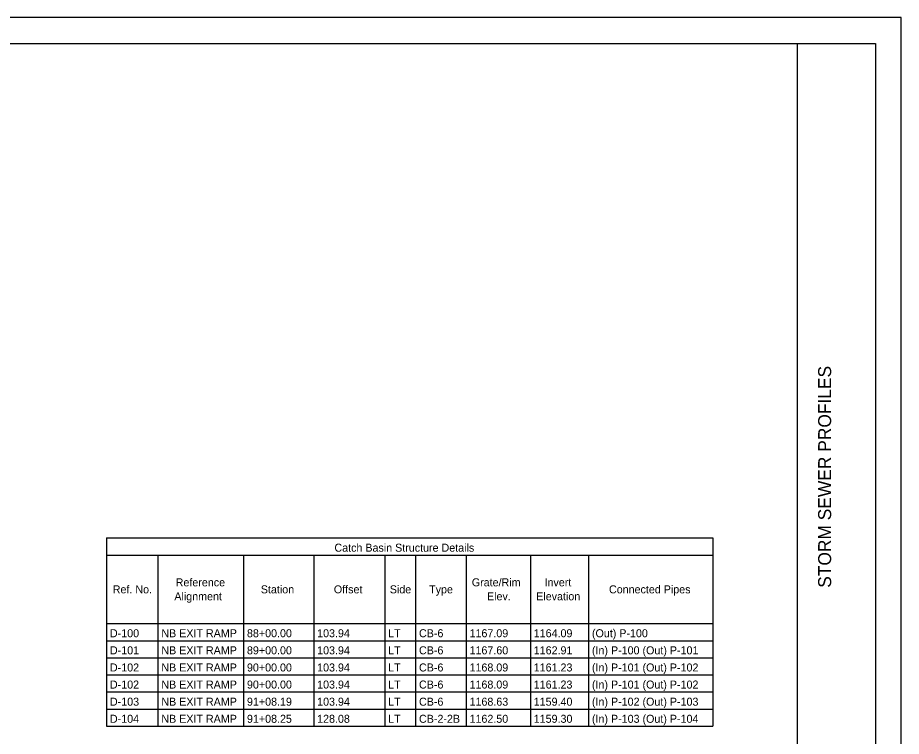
# Model space of a CAD drawing. Extents: x 0 to 34, y 0 to 22.
# Drawn here: x 17 to 34, y 8.16 to 22 of the extents above; entities that cross this region are included whole.
import ezdxf

# ---------------------------------------------------------------- set-up
doc = ezdxf.new("R2010")
doc.units = 0
for name, color, linetype in [('PF_P_Sta_Elev_Text', 7, 'Continuous'), ('SH_Border', 7, 'Continuous'), ('SH_Cut_Line', 7, 'Continuous'), ('SH_Data', 7, 'Continuous')]:
    doc.layers.add(name, color=color, linetype=linetype)

msp = doc.modelspace()

# ---------------------------------------------------------------- linework, layer by layer
at = {"layer": 'PF_P_Sta_Elev_Text'}
for p, q in [((18.71, 11.982), (30.371, 11.982)), ((18.71, 11.982), (18.71, 8.358)), ((30.371, 11.982), (30.371, 8.358)), ((18.71, 11.652), (30.371, 11.652)), ((19.698, 11.652), (19.698, 8.358)), ((21.345, 11.652), (21.345, 8.358)), ((22.695, 11.652), (22.695, 8.358)), ((24.063, 11.652), (24.063, 8.358)), ((24.655, 11.652), (24.655, 8.358)), ((25.627, 11.652), (25.627, 8.358)), ((26.863, 11.652), (26.863, 8.358)), ((27.983, 11.652), (27.983, 8.358)), ((18.71, 10.335), (30.371, 10.335)), ((18.71, 10.005), (30.371, 10.005)), ((18.71, 9.676), (30.371, 9.676)), ((18.71, 9.346), (30.371, 9.346)), ((18.71, 9.017), (30.371, 9.017)), ((18.71, 8.687), (30.371, 8.687)), ((18.71, 8.358), (30.371, 8.358))]:
    msp.add_line(p, q, dxfattribs=at)
at = {"layer": 'SH_Border'}
msp.add_line((32, 0.5), (32, 21.5), dxfattribs=at)
msp.add_lwpolyline([(1.5, 21.5), (33.5, 21.5), (33.5, 0.5), (1.5, 0.5)], close=True, dxfattribs=at)
at = {"layer": 'SH_Cut_Line'}
msp.add_lwpolyline([(0, 0), (34, 0), (34, 22), (0, 22)], close=True, dxfattribs=at)

# ---------------------------------------------------------------- texts
at = {"layer": 'PF_P_Sta_Elev_Text'}
for s, p in [('Catch Basin Structure Details', (23.094, 11.718)), ('Ref. No.', (18.829, 10.916)), ('Reference ', (20.04, 11.051)), ('Station', (21.678, 10.916)), ('Offset', (23.083, 10.916)), ('Side', (24.159, 10.916)), ('Type', (24.916, 10.916)), ('Grate/Rim ', (25.737, 11.051)), ('Invert ', (27.136, 11.051)), ('Connected Pipes', (28.376, 10.916)), ('Alignment', (20.014, 10.782)), ('Elev.', (26.029, 10.782)), ('Elevation', (26.976, 10.782)), ('D-100', (18.775, 10.071)), ('NB EXIT RAMP', (19.764, 10.071)), ('88+00.00', (21.411, 10.071)), ('103.94', (22.761, 10.071)), ('LT', (24.128, 10.071)), ('CB-6', (24.721, 10.071)), ('1167.09', (25.693, 10.071)), ('1164.09', (26.928, 10.071)), ('(Out) P-100', (28.048, 10.071)), ('D-101', (18.775, 9.742)), ('NB EXIT RAMP', (19.764, 9.742)), ('89+00.00', (21.411, 9.742)), ('103.94', (22.761, 9.742)), ('LT', (24.128, 9.742)), ('CB-6', (24.721, 9.742)), ('1167.60', (25.693, 9.742)), ('1162.91', (26.928, 9.742)), ('(In) P-100 (Out) P-101', (28.048, 9.742)), ('D-102', (18.775, 9.412)), ('NB EXIT RAMP', (19.764, 9.412)), ('90+00.00', (21.411, 9.412)), ('103.94', (22.761, 9.412)), ('LT', (24.128, 9.412)), ('CB-6', (24.721, 9.412)), ('1168.09', (25.693, 9.412)), ('1161.23', (26.928, 9.412)), ('(In) P-101 (Out) P-102', (28.048, 9.412)), ('D-102', (18.775, 9.083)), ('NB EXIT RAMP', (19.764, 9.083)), ('90+00.00', (21.411, 9.083)), ('103.94', (22.761, 9.083)), ('LT', (24.128, 9.083)), ('CB-6', (24.721, 9.083)), ('1168.09', (25.693, 9.083)), ('1161.23', (26.928, 9.083)), ('(In) P-101 (Out) P-102', (28.048, 9.083)), ('D-103', (18.775, 8.753)), ('NB EXIT RAMP', (19.764, 8.753)), ('91+08.19', (21.411, 8.753)), ('103.94', (22.761, 8.753)), ('LT', (24.128, 8.753)), ('CB-6', (24.721, 8.753)), ('1168.63', (25.693, 8.753)), ('1159.40', (26.928, 8.753)), ('(In) P-102 (Out) P-103', (28.048, 8.753)), ('D-104', (18.775, 8.424)), ('NB EXIT RAMP', (19.764, 8.424)), ('91+08.25', (21.411, 8.424)), ('128.08', (22.761, 8.424)), ('LT', (24.128, 8.424)), ('CB-2-2B', (24.721, 8.424)), ('1162.50', (25.693, 8.424)), ('1159.30', (26.928, 8.424)), ('(In) P-103 (Out) P-104', (28.048, 8.424))]:
    msp.add_text(s, height=0.154, dxfattribs=at).set_placement(p)
at = {"layer": 'SH_Data'}
msp.add_text('STORM SEWER PROFILES', height=0.25, rotation=90, dxfattribs=at).set_placement((32.65, 11.023))

doc.saveas('drawing.dxf')
